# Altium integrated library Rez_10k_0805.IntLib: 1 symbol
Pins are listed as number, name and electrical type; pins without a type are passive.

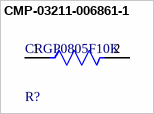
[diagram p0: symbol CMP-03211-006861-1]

## CMP-03211-006861-1
designator R?, comment CRGP0805F10K
CRGP 0805 10K 1%; Manufacturer: TE; Power Rating: 0.33W; Voltage Rating: 150V; Value: 10KΩ; Tolerance: 0.01; Temperature Coefficient: ±100ppm/°C
footprint FP-CRGP0805-IPC_A
footprint FP-CRGP0805-IPC_C
footprint FP-CRGP0805-IPC_B
pins: 1, 2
